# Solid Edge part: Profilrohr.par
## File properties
Username: ahadarics
Dokumentum tartalom típus: 0
Author: ahadarics
Last saved by: ahadarics
Revision: 86
Sűrűség: 0,000 kg/m^3
Pontosság: 0,990
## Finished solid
Body 1: solid body, 6 faces, 6 edges, 0 vertices.
  Faces by surface: cone 2, cylinder 2, plane 2
  Edges by curve: circle 6
Bounding box of the edges (mm): 21.270 x 21.270 x 432.000, from (-10.635, -10.635, -411) to (10.635, 10.635, 21).
Cylindrical faces by radius (mm): R10 x1, R10.635 x1
Conical faces (half-angle, radius in mm at the cone's reference point): 15 deg R10.067 x2
Planar faces by outward normal: +z 1, -z 1
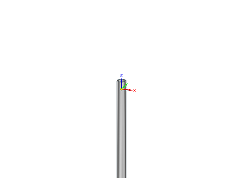
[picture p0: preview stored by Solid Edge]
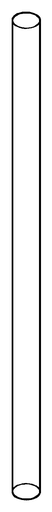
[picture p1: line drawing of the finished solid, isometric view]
